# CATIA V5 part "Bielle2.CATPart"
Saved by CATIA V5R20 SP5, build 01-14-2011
Part number: Bielle2
Bounding box of the stored display mesh (mm): x -5.967 to 5.967, y -2 to 44.924, z -5.999 to 5.999
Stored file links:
  F:\PROJ IAO\CATIA\Bielle2.CATPart
  F:\PROJ IAO\CATIA\Assemblage.CATProduct
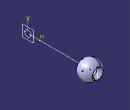
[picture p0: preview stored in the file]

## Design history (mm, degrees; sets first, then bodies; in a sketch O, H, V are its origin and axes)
Set1
  Plane1: linked copy from another document
  Line1: linked copy from another document
  Point1: linked copy from another document
Body1 (main body)
  Sketch1 on Plane1, origin (0, 0, 0), H (0, 1, 0), V (0, 0, 1)
    arc A1 centre (40, 0) radius 6 from (44.9239, 3.4286) to (35.0761, 3.4286) ccw
    point P1 (40, 0)
    reference projected point E1 (40, 0) from Point1
    arc A2 centre (40, 0) radius 3.1623 from (42.4495, 2) to (37.5505, 2) ccw
    point P4 (40, 0)
    point P5 (42.4495, 2)
    point P6 (37.5505, 2)
    reference projected point E2 (40, 0) from Point1
    line L1 (44.9239, 3.4286) -> (42.4495, 2)
    line L2 (37.5505, 2) -> (35.0761, 3.4286)
    reference projected line E3 (40, 0) -> (0, 0) from Line1
    reference projected line E4 (40, 0) -> (0, 0) from Line1
    reference projected line E5 (40, 0) -> (0, 0) from Line1
    reference projected line E6 (40, 0) -> (0, 0) from Line1
    radius A1 = 6
    angle L2 E3 = 30
    distance P6 E4 = 2
    angle L1 E5 = 30
    distance P5 E6 = 2
    coincidence: P1 H, P1 E1, P4 E2
  Shaft1: profile Sketch1, axis Line1, angle 360
  Sketch2 on Plane1, origin (0, 0, 0), H (0, 1, 0), V (0, 0, 1)
    circle A1 centre (0, 0) radius 2
    projected line E1 (44.9239, -3.4286) -> (44.9239, 3.4286) from edge [face of Shaft1 from Sketch1.L1 | face of Shaft1 from Sketch1.A1]
    projected line E2 (35.0761, -3.4286) -> (35.0761, 3.4286) from edge [face of Shaft1 from Sketch1.A1 | face of Shaft1 from Sketch1.L2]
    radius A1 = 2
